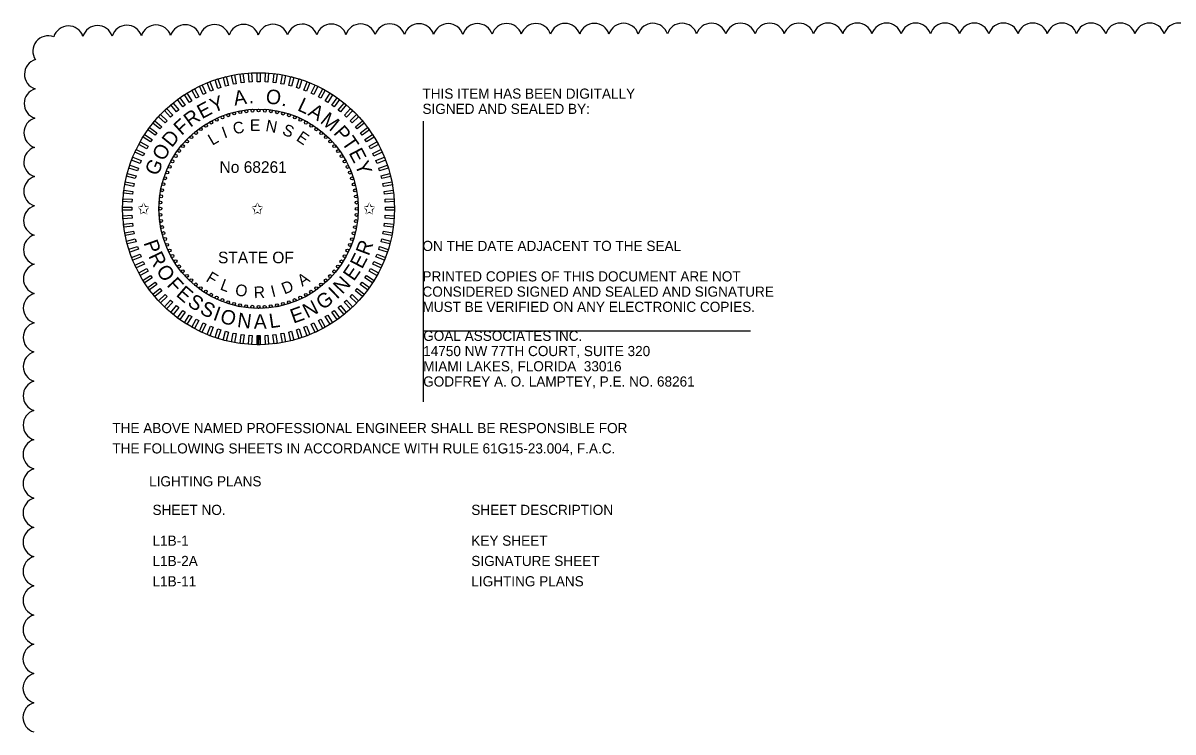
# Model space of a CAD drawing. Extents: x -811.2 to -795, y -2295.2 to -2235.1.
# Drawn here: x -811.11 to -803.18, y -2252.32 to -2247.44 of the extents above; entities that cross this region are included whole.
import ezdxf

# ---------------------------------------------------------------- set-up
doc = ezdxf.new("R2010")
doc.units = 0
for name, color, linetype in [('AdhocPoint_dp', 7, 'Continuous'), ('Cloud_dp', 7, 'Continuous'), ('PlotBorder_dp', 7, 'Continuous'), ('TextMinor', 7, 'Continuous'), ('TextMisc', 7, 'Continuous'), ('TextShtNo', 7, 'Continuous')]:
    doc.layers.add(name, color=color, linetype=linetype)

msp = doc.modelspace()

# ---------------------------------------------------------------- linework, layer by layer
at = {"layer": 'AdhocPoint_dp'}
for p, q in [((-808.3546, -2248.1122), (-808.3546, -2250.0469)), ((-808.3546, -2249.5569), (-806.0979, -2249.5569))]:
    msp.add_line(p, q, dxfattribs=at)
at = {"layer": 'Cloud_dp'}
for centre, start, end in [((-810.8012, -2247.5613), 18.59454, 163.59454), ((-810.5999, -2247.5581), 18.21421, 163.21421), ((-810.3985, -2247.5559), 18.04696, 163.04696), ((-810.197, -2247.5542), 17.94666, 162.94666), ((-809.9955, -2247.5527), 17.87787, 162.87787), ((-809.794, -2247.5515), 17.82689, 162.82689), ((-809.5924, -2247.5504), 17.78716, 162.78716), ((-809.3909, -2247.5495), 17.75505, 162.75505), ((-809.1894, -2247.5486), 17.72841, 162.72841), ((-808.9878, -2247.5478), 17.70584, 162.70584), ((-808.7863, -2247.5471), 17.6864, 162.6864), ((-808.5848, -2247.5465), 17.66942, 162.66942), ((-808.3832, -2247.546), 17.65443, 162.65443), ((-808.1817, -2247.5454), 17.64106, 162.64106), ((-807.9801, -2247.545), 17.62905, 162.62905), ((-807.7786, -2247.5445), 17.61817, 162.61817), ((-807.577, -2247.5441), 17.60826, 162.60826), ((-807.3755, -2247.5438), 17.59919, 162.59919), ((-807.174, -2247.5434), 17.59084, 162.59084), ((-806.9724, -2247.5431), 17.58312, 162.58312), ((-806.7709, -2247.5428), 17.57595, 162.57595), ((-806.5693, -2247.5426), 17.56928, 162.56928), ((-806.3678, -2247.5424), 17.56305, 162.56305), ((-806.1662, -2247.5421), 17.55721, 162.55721), ((-805.9647, -2247.5419), 17.55172, 162.55172), ((-805.7631, -2247.5418), 17.54655, 162.54655), ((-805.5616, -2247.5416), 17.54167, 162.54167), ((-805.3601, -2247.5415), 17.53705, 162.53705), ((-805.1585, -2247.5414), 17.53267, 162.53267), ((-804.957, -2247.5413), 17.52851, 162.52851), ((-804.7554, -2247.5412), 17.52455, 162.52455), ((-804.5539, -2247.5411), 17.52079, 162.52079), ((-804.3523, -2247.541), 17.51719, 162.51719), ((-804.1508, -2247.541), 17.51375, 162.51375), ((-803.9492, -2247.5409), 17.51046, 162.51046), ((-803.7477, -2247.5409), 17.50731, 162.50731), ((-803.5461, -2247.5409), 17.50428, 162.50428), ((-803.3446, -2247.5409), 17.50138, 162.50138), ((-803.143, -2247.5409), 17.5, 162.5), ((-810.9414, -2247.6297), 68.43954, 213.43954), ((-810.999, -2247.7891), 106.80445, 251.80445), ((-811.001, -2247.9905), 107.04367, 252.04367), ((-811.0025, -2248.192), 107.15618, 252.15618), ((-811.0035, -2248.3935), 107.22533, 252.22533), ((-811.0044, -2248.595), 107.27338, 252.27338), ((-811.0052, -2248.7966), 107.30928, 252.30928), ((-811.0058, -2248.9981), 107.33743, 252.33743), ((-811.0063, -2249.1996), 107.36027, 252.36027), ((-811.0068, -2249.4012), 107.37928, 252.37928), ((-811.0072, -2249.6027), 107.39543, 252.39543), ((-811.0075, -2249.8042), 107.40937, 252.40937), ((-811.0078, -2250.0058), 107.42156, 252.42156), ((-811.0081, -2250.2073), 107.43234, 252.43234), ((-811.0083, -2250.4089), 107.44197, 252.44197), ((-811.0085, -2250.6104), 107.45063, 252.45063), ((-811.0086, -2250.812), 107.45847, 252.45847), ((-811.0088, -2251.0135), 107.46563, 252.46563), ((-811.0089, -2251.2151), 107.47218, 252.47218), ((-811.009, -2251.4166), 107.47822, 252.47822), ((-811.009, -2251.6181), 107.4838, 252.4838), ((-811.0091, -2251.8197), 107.48899, 252.48899), ((-811.0091, -2252.0212), 107.49382, 252.49382), ((-811.0091, -2252.2228), 107.49843, 252.49843)]:
    msp.add_arc(centre, 0.1057, start, end, dxfattribs=at)
at = {"layer": 'TextMinor'}
for radius in [0.9375, 0.6875]:
    msp.add_circle((-809.4901, -2248.7156), radius, dxfattribs=at)
at = {"layer": 'TextShtNo'}
for p, q in [((-809.5001, -2249.6532), (-809.5003, -2249.5907)), ((-809.4901, -2249.6531), (-809.4903, -2249.5906)), ((-809.4801, -2249.6531), (-809.4803, -2249.5906))]:
    msp.add_line(p, q, dxfattribs=at)
for points in [[(-809.5897, -2247.8462), (-809.6097, -2247.8488), (-809.6175, -2247.7868), (-809.5975, -2247.7843)], [(-809.5349, -2247.8417), (-809.555, -2247.843), (-809.559, -2247.7806), (-809.5388, -2247.7794)], [(-809.4799, -2247.8406), (-809.5001, -2247.8406), (-809.5001, -2247.7782), (-809.4799, -2247.7782)], [(-809.425, -2247.843), (-809.4452, -2247.8417), (-809.4412, -2247.7794), (-809.4211, -2247.7807)], [(-809.3703, -2247.8488), (-809.3904, -2247.8463), (-809.3825, -2247.7843), (-809.3625, -2247.7868)], [(-809.8535, -2247.9195), (-809.8717, -2247.9281), (-809.8983, -2247.8716), (-809.8801, -2247.863)], [(-809.8028, -2247.8983), (-809.8215, -2247.9057), (-809.8445, -2247.8477), (-809.8258, -2247.8402)], [(-809.7508, -2247.8803), (-809.77, -2247.8865), (-809.7893, -2247.8271), (-809.7701, -2247.8209)], [(-809.6979, -2247.8656), (-809.7174, -2247.8706), (-809.7329, -2247.8101), (-809.7134, -2247.8051)], [(-809.6441, -2247.8542), (-809.6639, -2247.858), (-809.6756, -2247.7966), (-809.6558, -2247.7929)], [(-809.3162, -2247.858), (-809.336, -2247.8542), (-809.3243, -2247.7929), (-809.3045, -2247.7967)], [(-809.2626, -2247.8706), (-809.2822, -2247.8656), (-809.2667, -2247.8051), (-809.2471, -2247.8102)], [(-809.21, -2247.8866), (-809.2292, -2247.8803), (-809.2099, -2247.821), (-809.1907, -2247.8272)], [(-809.1585, -2247.9058), (-809.1773, -2247.8984), (-809.1543, -2247.8403), (-809.1355, -2247.8477)], [(-809.1083, -2247.9282), (-809.1266, -2247.9196), (-809.1, -2247.8631), (-809.0817, -2247.8717)], [(-809.9504, -2247.9714), (-809.9674, -2247.9822), (-810.0009, -2247.9295), (-809.9838, -2247.9186)], [(-809.9027, -2247.9439), (-809.9204, -2247.9537), (-809.9505, -2247.8989), (-809.9328, -2247.8892)], [(-809.0596, -2247.9537), (-809.0773, -2247.944), (-809.0473, -2247.8893), (-809.0296, -2247.899)], [(-809.0127, -2247.9823), (-809.0297, -2247.9715), (-808.9962, -2247.9187), (-808.9792, -2247.9296)], [(-810.0817, -2248.0708), (-810.0964, -2248.0846), (-810.1392, -2248.0391), (-810.1244, -2248.0253)], [(-810.04, -2248.0349), (-810.0556, -2248.0478), (-810.0954, -2247.9997), (-810.0798, -2247.9868)], [(-809.9962, -2248.0017), (-810.0125, -2248.0136), (-810.0492, -2247.9631), (-810.0329, -2247.9512)], [(-808.9676, -2248.0137), (-808.9839, -2248.0018), (-808.9472, -2247.9513), (-808.9308, -2247.9632)], [(-808.9245, -2248.0479), (-808.9401, -2248.035), (-808.9003, -2247.9869), (-808.8847, -2247.9998)], [(-808.8837, -2248.0847), (-808.8984, -2248.0709), (-808.8557, -2248.0254), (-808.841, -2248.0392)], [(-810.121, -2248.1092), (-810.1348, -2248.1239), (-810.1804, -2248.0812), (-810.1665, -2248.0665)], [(-808.8453, -2248.1241), (-808.8591, -2248.1093), (-808.8136, -2248.0666), (-808.7998, -2248.0813)], [(-810.192, -2248.1931), (-810.2039, -2248.2094), (-810.2544, -2248.1727), (-810.2426, -2248.1564)], [(-810.1579, -2248.15), (-810.1707, -2248.1656), (-810.2188, -2248.1258), (-810.206, -2248.1102)], [(-808.8094, -2248.1657), (-808.8223, -2248.1502), (-808.7742, -2248.1104), (-808.7613, -2248.1259)], [(-808.7762, -2248.2095), (-808.7881, -2248.1932), (-808.7376, -2248.1565), (-808.7257, -2248.1728)], [(-810.252, -2248.2852), (-810.2617, -2248.3028), (-810.3164, -2248.2728), (-810.3067, -2248.2551)], [(-810.2235, -2248.2382), (-810.2343, -2248.2552), (-810.287, -2248.2218), (-810.2762, -2248.2047)], [(-808.7459, -2248.2554), (-808.7567, -2248.2383), (-808.7039, -2248.2049), (-808.6931, -2248.2219)], [(-808.7184, -2248.303), (-808.7281, -2248.2853), (-808.6734, -2248.2552), (-808.6637, -2248.2729)], [(-810.2775, -2248.3338), (-810.2861, -2248.3521), (-810.3426, -2248.3255), (-810.334, -2248.3073)], [(-808.694, -2248.3523), (-808.7026, -2248.334), (-808.6461, -2248.3074), (-808.6375, -2248.3257)], [(-810.3192, -2248.4355), (-810.3254, -2248.4547), (-810.3848, -2248.4355), (-810.3786, -2248.4163)], [(-810.3, -2248.384), (-810.3074, -2248.4028), (-810.3654, -2248.3798), (-810.358, -2248.3611)], [(-808.6728, -2248.403), (-808.6802, -2248.3842), (-808.6222, -2248.3612), (-808.6147, -2248.38)], [(-808.6548, -2248.4549), (-808.661, -2248.4357), (-808.6016, -2248.4164), (-808.5954, -2248.4356)], [(-810.3351, -2248.4882), (-810.3401, -2248.5077), (-810.4006, -2248.4922), (-810.3956, -2248.4726)], [(-808.64, -2248.5079), (-808.6451, -2248.4883), (-808.5846, -2248.4728), (-808.5796, -2248.4924)], [(-810.3477, -2248.5417), (-810.3515, -2248.5615), (-810.4129, -2248.5498), (-810.4091, -2248.53)], [(-808.6287, -2248.5617), (-808.6325, -2248.5418), (-808.5711, -2248.5301), (-808.5673, -2248.55)], [(-810.3628, -2248.6505), (-810.3641, -2248.6707), (-810.4264, -2248.6668), (-810.4251, -2248.6466)], [(-810.357, -2248.5959), (-810.3595, -2248.6159), (-810.4215, -2248.6081), (-810.4189, -2248.588)], [(-808.6207, -2248.6161), (-808.6232, -2248.596), (-808.5613, -2248.5882), (-808.5588, -2248.6082)], [(-808.6162, -2248.6709), (-808.6174, -2248.6507), (-808.5551, -2248.6468), (-808.5539, -2248.6669)], [(-810.3652, -2248.7054), (-810.3652, -2248.7256), (-810.4276, -2248.7256), (-810.4276, -2248.7054)], [(-808.6151, -2248.7258), (-808.6151, -2248.7056), (-808.5527, -2248.7056), (-808.5527, -2248.7258)], [(-810.3641, -2248.7604), (-810.3628, -2248.7806), (-810.4251, -2248.7845), (-810.4264, -2248.7643)], [(-810.3595, -2248.8152), (-810.357, -2248.8352), (-810.4189, -2248.8431), (-810.4215, -2248.823)], [(-808.6233, -2248.8354), (-808.6207, -2248.8154), (-808.5588, -2248.8232), (-808.5613, -2248.8432)], [(-808.6175, -2248.7807), (-808.6162, -2248.7606), (-808.5539, -2248.7645), (-808.5551, -2248.7847)], [(-810.3516, -2248.8696), (-810.3478, -2248.8894), (-810.4091, -2248.9011), (-810.4129, -2248.8813)], [(-808.6325, -2248.8896), (-808.6287, -2248.8698), (-808.5674, -2248.8815), (-808.5712, -2248.9013)], [(-810.3402, -2248.9234), (-810.3352, -2248.9429), (-810.3957, -2248.9585), (-810.4007, -2248.9389)], [(-810.3255, -2248.9763), (-810.3192, -2248.9955), (-810.3786, -2249.0148), (-810.3849, -2248.9956)], [(-808.6611, -2248.9957), (-808.6548, -2248.9765), (-808.5954, -2248.9958), (-808.6017, -2249.015)], [(-808.6451, -2248.9431), (-808.6401, -2248.9236), (-808.5796, -2248.9391), (-808.5846, -2248.9586)], [(-810.3075, -2249.0283), (-810.3, -2249.0471), (-810.3581, -2249.07), (-810.3655, -2249.0513)], [(-808.6803, -2249.0472), (-808.6729, -2249.0285), (-808.6148, -2249.0514), (-808.6222, -2249.0702)], [(-810.2862, -2249.079), (-810.2776, -2249.0973), (-810.3341, -2249.1238), (-810.3427, -2249.1056)], [(-810.2618, -2249.1283), (-810.2521, -2249.1459), (-810.3068, -2249.176), (-810.3165, -2249.1583)], [(-808.7282, -2249.1461), (-808.7185, -2249.1284), (-808.6638, -2249.1585), (-808.6735, -2249.1762)], [(-808.7027, -2249.0974), (-808.6941, -2249.0792), (-808.6376, -2249.1057), (-808.6462, -2249.124)], [(-810.2344, -2249.1759), (-810.2236, -2249.1929), (-810.2763, -2249.2264), (-810.2871, -2249.2094)], [(-808.7568, -2249.1931), (-808.746, -2249.1761), (-808.6932, -2249.2095), (-808.704, -2249.2266)], [(-810.204, -2249.2217), (-810.1922, -2249.2381), (-810.2427, -2249.2748), (-810.2545, -2249.2584)], [(-810.1708, -2249.2656), (-810.158, -2249.2811), (-810.2061, -2249.3209), (-810.2189, -2249.3054)], [(-808.8224, -2249.2812), (-808.8095, -2249.2657), (-808.7614, -2249.3055), (-808.7743, -2249.321)], [(-808.7882, -2249.2382), (-808.7763, -2249.2219), (-808.7258, -2249.2586), (-808.7377, -2249.2749)], [(-810.135, -2249.3072), (-810.1211, -2249.3219), (-810.1667, -2249.3647), (-810.1805, -2249.35)], [(-810.0965, -2249.3465), (-810.0818, -2249.3603), (-810.1246, -2249.4059), (-810.1393, -2249.392)], [(-808.8985, -2249.3605), (-808.8838, -2249.3467), (-808.8411, -2249.3922), (-808.8558, -2249.406)], [(-808.8592, -2249.3221), (-808.8454, -2249.3073), (-808.7999, -2249.3501), (-808.8137, -2249.3648)], [(-810.0557, -2249.3834), (-810.0402, -2249.3962), (-810.08, -2249.4443), (-810.0955, -2249.4315)], [(-810.0127, -2249.4176), (-809.9964, -2249.4294), (-810.0331, -2249.4799), (-810.0494, -2249.4681)], [(-809.9676, -2249.449), (-809.9505, -2249.4598), (-809.984, -2249.5125), (-810.001, -2249.5017)], [(-809.0299, -2249.4599), (-809.0128, -2249.4491), (-808.9794, -2249.5018), (-808.9964, -2249.5126)], [(-808.984, -2249.4295), (-808.9677, -2249.4177), (-808.931, -2249.4682), (-808.9473, -2249.4801)], [(-808.9402, -2249.3964), (-808.9247, -2249.3835), (-808.8848, -2249.4316), (-808.9004, -2249.4445)], [(-809.9206, -2249.4775), (-809.9029, -2249.4872), (-809.933, -2249.542), (-809.9507, -2249.5322)], [(-809.8719, -2249.503), (-809.8536, -2249.5116), (-809.8802, -2249.5681), (-809.8985, -2249.5595)], [(-809.8217, -2249.5255), (-809.8029, -2249.5329), (-809.8259, -2249.591), (-809.8447, -2249.5835)], [(-809.1775, -2249.533), (-809.1587, -2249.5255), (-809.1357, -2249.5836), (-809.1545, -2249.591)], [(-809.1268, -2249.5117), (-809.1085, -2249.5031), (-809.0819, -2249.5596), (-809.1002, -2249.5682)], [(-809.0775, -2249.4873), (-809.0598, -2249.4776), (-809.0297, -2249.5323), (-809.0474, -2249.5421)], [(-809.7702, -2249.5447), (-809.751, -2249.5509), (-809.7703, -2249.6103), (-809.7895, -2249.6041)], [(-809.7176, -2249.5606), (-809.698, -2249.5657), (-809.7136, -2249.6261), (-809.7331, -2249.6211)], [(-809.6641, -2249.5733), (-809.6443, -2249.577), (-809.656, -2249.6384), (-809.6758, -2249.6346)], [(-809.6099, -2249.5825), (-809.5899, -2249.585), (-809.5977, -2249.647), (-809.6177, -2249.6444)], [(-809.5552, -2249.5883), (-809.5351, -2249.5896), (-809.539, -2249.6519), (-809.5592, -2249.6506)], [(-809.5003, -2249.5907), (-809.4801, -2249.5907), (-809.4801, -2249.6531), (-809.5003, -2249.6531)], [(-809.4453, -2249.5896), (-809.4252, -2249.5883), (-809.4213, -2249.6506), (-809.4414, -2249.6519)], [(-809.3906, -2249.585), (-809.3705, -2249.5825), (-809.3627, -2249.6445), (-809.3827, -2249.647)], [(-809.3362, -2249.5771), (-809.3163, -2249.5733), (-809.3046, -2249.6346), (-809.3245, -2249.6384)], [(-809.2824, -2249.5657), (-809.2628, -2249.5607), (-809.2473, -2249.6212), (-809.2668, -2249.6262)], [(-809.2294, -2249.551), (-809.2102, -2249.5447), (-809.1909, -2249.6041), (-809.2101, -2249.6104)]]:
    msp.add_lwpolyline(points, close=True, dxfattribs=at)
for centre in [(-809.7781, -2248.1024), (-809.739, -2248.0855), (-809.6989, -2248.0712), (-809.6581, -2248.0593), (-809.6165, -2248.0501), (-809.5745, -2248.0434), (-809.5321, -2248.0395), (-809.4896, -2248.0382), (-809.447, -2248.0395), (-809.4047, -2248.0436), (-809.3626, -2248.0503), (-809.3211, -2248.0596), (-809.2802, -2248.0715), (-809.2402, -2248.0859), (-809.2012, -2248.1029), (-809.9215, -2248.1933), (-809.8879, -2248.1672), (-809.8527, -2248.1433), (-809.816, -2248.1217), (-809.1633, -2248.1222), (-809.1266, -2248.1439), (-809.0915, -2248.1679), (-809.0579, -2248.194), (-809.9836, -2248.2515), (-809.9535, -2248.2214), (-809.026, -2248.2222), (-808.9959, -2248.2523), (-810.0618, -2248.3522), (-810.0379, -2248.317), (-810.0118, -2248.2834), (-808.9678, -2248.2842), (-808.9417, -2248.3179), (-808.9178, -2248.3531), (-810.1029, -2248.4267), (-810.0835, -2248.3888), (-808.8962, -2248.3898), (-808.8769, -2248.4277), (-810.1343, -2248.5057), (-810.1198, -2248.4657), (-808.86, -2248.4668), (-808.8456, -2248.5068), (-810.1555, -2248.5881), (-810.1462, -2248.5466), (-808.8338, -2248.5477), (-808.8245, -2248.5892), (-810.1622, -2248.6302), (-808.8179, -2248.6313), (-810.1676, -2248.7151), (-810.1662, -2248.6725), (-808.814, -2248.6737), (-808.8127, -2248.7162), (-810.1663, -2248.7576), (-810.1623, -2248.8), (-808.8181, -2248.8011), (-808.814, -2248.7587), (-810.1557, -2248.842), (-810.1464, -2248.8836), (-808.8341, -2248.8847), (-808.8248, -2248.8431), (-810.1346, -2248.9244), (-810.1202, -2248.9645), (-808.8604, -2248.9656), (-808.846, -2248.9255), (-810.1034, -2249.0036), (-810.0841, -2249.0415), (-808.8967, -2249.0425), (-808.8774, -2249.0046), (-810.0624, -2249.0782), (-810.0385, -2249.1134), (-808.9424, -2249.1143), (-808.9184, -2249.0791), (-810.0125, -2249.147), (-809.9844, -2249.179), (-809.9543, -2249.2091), (-809.0268, -2249.2099), (-808.9967, -2249.1798), (-808.9685, -2249.1479), (-809.9224, -2249.2373), (-809.8888, -2249.2634), (-809.8536, -2249.2873), (-809.1276, -2249.2879), (-809.0924, -2249.264), (-809.0587, -2249.238), (-809.817, -2249.309), (-809.7791, -2249.3284), (-809.74, -2249.3453), (-809.7, -2249.3598), (-809.6591, -2249.3717), (-809.6176, -2249.381), (-809.3637, -2249.3812), (-809.3222, -2249.372), (-809.2813, -2249.3601), (-809.2413, -2249.3457), (-809.2022, -2249.3289), (-809.1642, -2249.3096), (-809.5756, -2249.3877), (-809.5332, -2249.3917), (-809.4901, -2249.3931), (-809.4481, -2249.3918), (-809.4058, -2249.3878)]:
    msp.add_circle(centre, 0.01, dxfattribs=at)

# ---------------------------------------------------------------- texts
at = {"layer": 'PlotBorder_dp'}
for s, p in [('THIS ITEM HAS BEEN DIGITALLY', (-808.3596, -2247.9571)), ('SIGNED AND SEALED BY:', (-808.3596, -2248.0621)), ('ON THE DATE ADJACENT TO THE SEAL', (-808.3596, -2249.0071)), ('PRINTED COPIES OF THIS DOCUMENT ARE NOT ', (-808.3596, -2249.2171)), ('CONSIDERED SIGNED AND SEALED AND SIGNATURE ', (-808.3596, -2249.3221)), ('MUST BE VERIFIED ON ANY ELECTRONIC COPIES.', (-808.3596, -2249.4271)), ('GOAL ASSOCIATES INC.', (-808.3546, -2249.6269)), ('14750 NW 77TH COURT, SUITE 320', (-808.3546, -2249.7319)), ('MIAMI LAKES, FLORIDA  33016', (-808.3546, -2249.8369)), ('GODFREY A. O. LAMPTEY, P.E. NO. 68261', (-808.3546, -2249.9419)), ('THE ABOVE NAMED PROFESSIONAL ENGINEER SHALL BE RESPONSIBLE FOR ', (-810.4987, -2250.2631)), ('THE FOLLOWING SHEETS IN ACCORDANCE WITH RULE 61G15-23.004, F.A.C.', (-810.4987, -2250.4031)), ('LIGHTING PLANS', (-810.245, -2250.6301))]:
    msp.add_text(s, height=0.07, dxfattribs=at).set_placement(p)
at = {"layer": 'TextMisc'}
for s, p in [('SHEET NO.', (-810.2215, -2250.8271)), ('SHEET DESCRIPTION', (-808.0226, -2250.8271)), ('L1B-1', (-810.2215, -2251.0393)), ('KEY SHEET', (-808.0226, -2251.0393)), ('L1B-2A', (-810.2215, -2251.1793)), ('SIGNATURE SHEET', (-808.0226, -2251.1793)), ('L1B-11', (-810.2215, -2251.3193)), ('LIGHTING PLANS', (-808.0226, -2251.3193))]:
    msp.add_text(s, height=0.07, dxfattribs=at).set_placement(p)
at = {"layer": 'TextShtNo'}
for s, height, rotation, p in [('Y', 0.1, 21.06329, (-809.8021, -2248.0562)), ('A', 0.1, 8.80884, (-809.6551, -2248.005)), ('O', 0.1, 352.18771, (-809.4449, -2247.9875)), ('E', 0.1, 28.10553, (-809.8806, -2248.0994)), ('.', 0.1, 1.04184, (-809.5575, -2247.9892)), ('.', 0.1, 343.52684, (-809.3358, -2248.0026)), ('L', 0.1, 334.67271, (-809.2279, -2248.0349)), ('A', 0.1, 328.40959, (-809.1552, -2248.0676)), ('F', 0.1, 42.37723, (-810.0205, -2248.2147)), ('R', 0.1, 35.92688, (-809.9609, -2248.1583)), ('E', 0.08, 0.41861, (-809.5498, -2248.1806)), ('N', 0.08, 349.29143, (-809.4455, -2248.1791)), ('M', 0.1, 320.6426, (-809.0707, -2248.1188)), ('D', 0.1, 50.8569, (-810.0886, -2248.2984)), ('I', 0.08, 20.01168, (-809.7258, -2248.2316)), ('C', 0.08, 12.20255, (-809.6579, -2248.204)), ('S', 0.08, 337.02207, (-809.3325, -2248.2008)), ('E', 0.08, 325.86633, (-809.2358, -2248.2411)), ('P', 0.1, 311.19658, (-808.9784, -2248.1957)), ('L', 0.08, 30.40215, (-809.8093, -2248.282)), ('T', 0.1, 304.45632, (-808.9209, -2248.2594)), ('O', 0.1, 59.51777, (-810.1446, -2248.3933)), ('E', 0.1, 297.63152, (-808.8707, -2248.3302)), ('G', 0.1, 68.0518, (-810.1851, -2248.494)), ('Y', 0.1, 290.58928, (-808.8281, -2248.4091)), ('P', 0.1, 289.40551, (-810.2848, -2248.9502)), ('R', 0.1, 69.5134, (-808.7299, -2249.0453)), ('R', 0.1, 296.14576, (-810.2518, -2249.0419)), ('E', 0.1, 62.47116, (-808.7761, -2249.136)), ('O', 0.1, 303.96711, (-810.2003, -2249.1425)), ('E', 0.1, 55.42892, (-808.833, -2249.2204)), ('F', 0.1, 312.62798, (-810.1279, -2249.2446)), ('F', 0.08, 328.72408, (-809.8582, -2249.2122)), ('L', 0.08, 339.29159, (-809.7609, -2249.2713)), ('D', 0.08, 22.01279, (-809.312, -2249.3075)), ('A', 0.08, 34.49917, (-809.1883, -2249.255)), ('N', 0.1, 47.17876, (-808.9123, -2249.3095)), ('E', 0.1, 319.07833, (-810.0645, -2249.3129)), ('O', 0.08, 349.68206, (-809.6562, -2249.311)), ('R', 0.08, 2.33977, (-809.5217, -2249.3329)), ('I', 0.08, 14.20366, (-809.3941, -2249.3262)), ('G', 0.1, 35.11153, (-809.0492, -2249.4172)), ('I', 0.1, 43.64556, (-808.9499, -2249.344)), ('S', 0.1, 326.12056, (-809.9869, -2249.3788)), ('S', 0.1, 333.193, (-809.9015, -2249.4349)), ('N', 0.1, 26.86136, (-809.1544, -2249.4732)), ('I', 0.1, 340.26543, (-809.8098, -2249.4801)), ('O', 0.1, 343.79863, (-809.7621, -2249.4983)), ('N', 0.1, 352.45949, (-809.6411, -2249.5304)), ('A', 0.1, 0.70966, (-809.5227, -2249.5436)), ('L', 0.1, 8.47665, (-809.4105, -2249.5404)), ('E', 0.1, 19.81912, (-809.2498, -2249.5086))]:
    msp.add_text(s, height=height, rotation=rotation, dxfattribs=at).set_placement(p)
for s, p in [('No 68261', (-809.7591, -2248.4684)), ('✩', (-810.3251, -2248.7536)), ('✩', (-809.5404, -2248.7536)), ('✩', (-808.7685, -2248.7536)), ('STATE OF', (-809.7698, -2249.0918))]:
    msp.add_text(s, height=0.08, dxfattribs=at).set_placement(p)

doc.saveas('drawing.dxf')
